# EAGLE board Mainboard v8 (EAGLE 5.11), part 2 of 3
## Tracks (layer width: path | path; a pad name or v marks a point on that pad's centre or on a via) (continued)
M1-B  (via drill 0.3) (continued)
  pour Bottom (no thermals): 101.12,68.42 103.98,68.42 103.98,69.69 106.52,69.69 106.52,65.25 101.12,65.25
  pour Bottom (no thermals): 114.14,78.9 111.92,78.9 110.49,77.47 110.49,65.41 110.33,65.25 109.7,65.25 109.7,77.95 111.6,79.85 114.14,79.85
  pour Top (no thermals): 105.89,69.69 110.49,69.69 110.49,65.25 105.89,65.25
M1-C  (via drill 0.3)
  Top 0.61: v100.17,61.75 100.17,63.34 C6.2 99.86,63.03 IC1.18
  Bottom 0.61: v100.17,61.75 Q5.3
  other vias: 110.02,63.03 110.02,61.75 110.02,60.48 110.02,59.22 110.97,59.22 110.97,60.48 110.97,61.75 110.97,63.03 106.2,63.03 106.2,61.75 106.2,60.48 106.2,59.22
  pour Top (no thermals): 105.89,63.34 111.28,63.34 111.28,58.9 105.89,58.9
  pour Bottom (no thermals): 101.12,62.07 103.98,62.07 103.98,63.34 106.52,63.34 106.52,58.9 101.12,58.9
  pour Bottom (no thermals): 114.14,77 112.24,77 111.76,76.52 111.76,59.69 110.97,58.9 109.7,58.9 109.7,63.03 110.97,64.3 110.97,76.68 112.24,77.95 114.14,77.95
M1-FLT  (via drill 0.3)
  Top 0.254: IC8.13 75.31,39.93 77.63,42.25 77.63,44.61 80.81,47.78 v82.08,47.78 | Q36.3 84.93,62.07 82.23,59.37 | 82.23,59.37 v82.08,59.22 82.23,59.37
  Bottom 0.254: v82.08,47.78 82.08,50.33 83.34,51.59 83.34,56.99 82.08,58.26 v82.08,59.22
M1-H1  (via drill 0.3)
  Top 0.254: IC16.116 73.36,78.09 76.36,75.09 78.9,75.09 | 78.9,75.09 80.49,75.09 83.66,78.27 103.03,78.27 106.2,81.44 113.83,81.44 114.14,81.76 116.36,81.76 116.68,82.08 v116.68,83.34 116.68,82.51 CN1.2 | IC10.13 78.9,73.28 78.9,75.09 | RN2.2 116.68,76.16 v116.68,77 | v116.68,80.17 116.68,79.33 RN1.2
  Bottom 0.254: v116.68,77 v116.68,80.17 v116.68,83.34
M1-H2  (via drill 0.3)
  Top 0.254: IC16.117 73.49,78.59 76.36,75.72 v79.06,75.72 80.17,75.72 83.34,78.9 102.87,78.9 105.89,81.92 113.67,81.92 115.09,83.34 v115.73,83.34 115.73,82.67 CN1.3 | IC10.12 79.53,73.26 79.53,73.98 v79.85,74.3 | RN2.3 115.73,76.32 v115.73,77 | v115.73,80.17 115.73,79.5 RN1.3
  Bottom 0.254: v79.06,75.72 79.85,74.93 v79.85,74.3 | v115.73,77 v115.73,80.17 v115.73,83.34
M1-H3  (via drill 0.3)
  Top 0.254: IC16.118 73.62,79.09 76.36,76.36 v79.85,76.36 83.03,79.53 102.55,79.53 105.41,82.39 113.51,82.39 115.09,83.98 117.32,83.98 117.64,83.66 v117.64,83.34 117.64,82.5 CN1.1 | IC10.9 81.47,74.17 v81.6,74.3 | RN2.1 117.64,76.15 v117.64,77 | v117.64,80.17 117.64,79.33 RN1.1
  Bottom 0.254: v117.64,77 v117.64,80.17 v117.64,83.34 | v79.85,76.36 79.85,76.04 v81.6,74.3
M1-HA  (via drill 0.3)
  Top 0.152: v88.11,81.44 78.58,81.44 78.27,81.76 73.5,81.76 73.17,82.09 IC16.124
  Top 0.406: v90.01,74.45 IC1.2
  Bottom 0.254: v88.11,81.44 88.11,76.36 v90.01,74.45
M1-HB  (via drill 0.3)
  Top 0.152: v86.84,82.71 78.58,82.71 78.27,82.39 74.14,82.39 73.44,83.09 IC16.126
  Top 0.406: v86.52,73.19 IC1.3
  Bottom 0.254: v86.84,82.71 86.84,75.72 86.52,75.41 v86.52,73.19
M1-HC  (via drill 0.3)
  Top 0.152: v85.57,83.98 78.58,83.98 77.63,83.03 74.77,83.03 73.7,84.09 IC16.128
  Top 0.406: v85.25,71.92 IC1.4
  Bottom 0.254: v85.57,83.98 85.57,76.36 85.25,76.04 v85.25,71.92
M1-LA  (via drill 0.3)
  Top 0.152: v87.47,82.08 73.82,82.08 73.3,82.59 IC16.125
  Top 0.406: v90.01,70.64 IC1.5
  Bottom 0.254: v87.47,82.08 87.47,73.19 v90.01,70.64
M1-LB  (via drill 0.3)
  Top 0.152: v86.2,83.34 78.58,83.34 77.95,82.71 74.45,82.71 73.57,83.59 IC16.127
  Top 0.406: v90.01,69.38 IC1.6
  Bottom 0.254: v86.2,83.34 86.2,76.04 85.89,75.72 85.89,72.55 89.06,69.38 v90.01,69.38
M1-LC  (via drill 0.3)
  Top 0.152: v84.93,84.61 78.58,84.61 77.31,83.34 75.09,83.34 73.84,84.59 IC16.129
  Top 0.254: IC1.7 89.06,68.11
  Top 0.406: v90.01,68.11 89.06,68.11 IC1.7
  Bottom 0.254: v84.93,84.61 84.93,76.68 84.61,76.36 84.61,71.6 88.11,68.11 v90.01,68.11
M1-PWR  (via drill 0.3)
  Top 0.406: IC26.5 v100.97,56.99
  Bottom 0.406: v106.52,56.99 105.89,56.99 105.25,56.99 v100.97,56.99
  other vias: 109.7,57.94 109.7,56.99 109.7,56.04
  pour Bottom (no thermals): 109.06,76.04 107.16,76.04 107.16,58.58 106.2,57.63 106.2,56.36 107.16,55.41 110.33,55.41 110.33,58.26 109.06,58.26
  pour Top (no thermals): 106.2,57.63 106.84,58.26 110.33,58.26 110.33,55.41 107.16,55.41 106.2,56.36
M2-A  (via drill 0.3)
  Top 0.61: v19.84,62.71 19.84,61.44 C12.2 20.16,61.75 IC2.26
  Bottom 0.61: v19.84,62.71 17.84,62.71 Q7.1
  other vias: 13.81,63.03 13.81,61.75 13.81,60.48 13.81,59.22 10,63.03 10,59.22 10,60.48 10,61.75 9.37,62.39 9.37,63.66
  pour Bottom (no thermals): 18.89,60.17 16.04,60.17 16.04,58.9 13.5,58.9 13.5,63.34 18.89,63.34
  pour Top (no thermals): 14.13,63.34 14.13,58.9 9.68,58.9 9.68,61.12 9.05,61.75 9.05,64.3 9.68,64.3 10.64,63.34
  pour Bottom (no thermals): 10.32,58.9 9.68,58.9 9.68,61.12 9.05,61.75 9.05,63.66 6.51,66.2 6.51,72.87 7.78,72.87 7.78,66.52 10.32,63.98
M2-A1  (via drill 0.3)
  Top 0.254: v60.48,85.89 62.07,85.89 66,89.82 IC16.10 | v47.15,69.69 37.94,60.48 IC2.2
  Bottom 0.254: v60.48,85.89 50.96,85.89 50.33,86.52 49.05,86.52 48.42,85.89 48.42,70.96 v47.15,69.69
M2-A2  (via drill 0.3)
  Top 0.254: v60.48,87.16 62.07,87.16 65,90.09 IC16.12 | v45.56,69.06 38.26,61.75 IC2.3
  Bottom 0.254: v60.48,87.16 50.96,87.16 50.33,87.79 49.05,87.79 47.15,85.89 47.15,75.72 45.88,74.45 45.88,69.38 v45.56,69.06
M2-A3  (via drill 0.3)
  Top 0.254: v60.48,88.42 62.07,88.42 64,90.36 IC16.14 | v44.61,69.06 38.58,63.03 IC2.4
  Bottom 0.254: v60.48,88.42 50.96,88.42 50.33,89.06 46.2,89.06 44.61,87.47 v44.61,69.06
M2-ADC
  Top 0.254: IC6.2 21.75,56.04 21.43,55.72 21.43,54.45 22.07,53.82 27.47,53.82 35.09,46.2 37.94,46.2 39.3,44.84 RN12.3
M2-AOUT
  Top 0.254: RN12.6 CN7.3 43.1,44.84 43.34,44.61 43.34,43.66 45.24,41.75 45.47,41.53 IC8.26
M2-B  (via drill 0.3)
  Top 0.61: v19.84,67.79 19.84,66.52 C13.2 20.16,66.83 IC2.22
  Bottom 0.61: Q9.2 17.84,67.79 | 17.84,67.79 Q9.3 | 17.84,67.79 v19.84,67.79
  other vias: 13.81,69.38 13.81,68.11 13.81,66.83 13.81,65.56 10,69.38 10,68.11 10,66.83 10,65.56 9.37,66.2 9.37,67.47 9.37,68.74
  pour Bottom (no thermals): 18.89,66.52 16.04,66.52 16.04,65.25 13.5,65.25 13.5,69.69 18.89,69.69
  pour Top (no thermals): 14.13,69.69 14.13,65.25 10,65.25 8.73,66.52 8.73,68.42 10,69.69
  pour Bottom (no thermals): 5.88,73.82 7.94,73.82 8.26,73.5 8.26,66.99 10,65.25 10.32,65.25 10.32,69.69 10,70.01 9.68,70.01 9.05,70.64 9.05,74.14 8.1,75.09 5.88,75.09
M2-B1  (via drill 0.3)
  Top 0.254: v61.12,86.52 62.07,86.52 65.5,89.95 IC16.11 | v47.15,70.64 45.24,70.64 38.74,64.14 32.55,64.14 32.39,64.3 IC2.5
  Bottom 0.254: v61.12,86.52 50.96,86.52 50.33,87.16 49.05,87.16 47.78,85.89 47.78,71.28 v47.15,70.64
M2-B2  (via drill 0.3)
  Top 0.254: v61.12,87.79 62.07,87.79 64.5,90.22 IC16.13 | v45.24,71.92 45.24,71.6 38.26,64.61 33.5,64.61 32.55,65.56 IC2.6
  Bottom 0.254: v61.12,87.79 50.96,87.79 50.33,88.42 46.2,88.42 45.24,87.47 v45.24,71.92
M2-B3  (via drill 0.3)
  Top 0.254: v61.12,89.06 62.07,89.06 63.5,90.49 IC16.15 | IC2.7 32.7,66.83 33.5,66.04 34.13,65.41 34.45,65.09 37.78,65.09 v43.98,71.28
  Bottom 0.254: v61.12,89.06 50.96,89.06 50.33,89.69 46.2,89.69 43.98,87.47 v43.98,71.28
M2-C  (via drill 0.3)
  Top 0.61: IC2.18 20.16,71.92 C14.2 19.84,71.59 v19.84,73.19
  Bottom 0.254: M2.6 7.78,77
  Bottom 0.61: M2.7 M2.6 | Q11.2 Q11.3 v19.84,73.19
  other vias: 13.81,75.72 13.81,74.45 13.81,73.19 13.81,71.92 10,75.72 10,74.45 10,73.19 9.37,75.09 10,71.92
  pour Bottom (no thermals): 18.89,72.87 16.04,72.87 16.04,71.6 13.5,71.6 13.5,76.04 18.89,76.04
  pour Top (no thermals): 14.13,71.6 14.13,76.04 10,76.04 10,73.5 9.37,72.87 9.37,71.6
  pour Bottom (no thermals): 5.88,76.04 7.78,76.04 9.53,74.3 9.53,71.76 9.68,71.6 10.16,71.6 10.32,71.76 10.32,75.72 9.05,77 5.88,77
M2-FLT  (via drill 0.3)
  Top 0.254: v38.26,42.7 38.26,42.07 40.96,39.37 51.59,39.37 55.09,35.88 59.69,35.88 61.34,37.53 IC8.31 | v38.26,67.95 37.31,66.98 Q37.3
  Bottom 0.254: v38.26,42.7 v38.26,67.95
M2-H1  (via drill 0.3)
  Top 0.254: v62.39,90.33 62.39,92.23 62,92.62 IC16.18 | IC11.12 39.52,87.81 v39.53,87.79 | RN4.2 4.29,79.73 v4.29,78.9 | v4.29,75.72 4.29,76.56 RN3.2 | CN2.2 4.29,73.38 v4.29,72.55 4.92,71.92 6.35,71.92 6.99,72.55 6.99,74.61 10,77.63 v27.78,77.63
  Bottom 0.254: v62.39,90.33 50.96,90.33 49.69,91.6 43.34,91.6 v39.53,87.79 29.37,77.63 v27.78,77.63 | v4.29,78.9 v4.29,75.72 v4.29,72.55
M2-H2  (via drill 0.3)
  Top 0.254: v61.75,89.69 61.75,92.23 61.5,92.48 IC16.19 | IC11.9 41.47,88.77 v41.44,88.74 | v3.34,75.72 3.34,76.36 | 3.34,76.36 3.34,76.4 | RN4.1 3.34,79.74 v3.34,78.9 | RN3.1 3.4,76.43 3.34,76.36 | CN2.1 3.34,73.39 v3.34,72.55 4.61,71.28 6.51,71.28 7.46,72.23 7.46,74.3 10.16,77 v28.42,77
  Bottom 0.254: v61.75,89.69 50.96,89.69 50.33,90.33 43.02,90.33 v41.44,88.74 29.69,77 v28.42,77 | v3.34,78.9 v3.34,75.72 v3.34,72.55
M2-H3  (via drill 0.3)
  Top 0.254: v61.12,90.97 61.12,92.23 61,92.35 IC16.20 | IC11.13 38.87,88.08 v38.58,87.79 | RN4.3 5.24,79.58 v5.24,78.9 | v5.24,75.72 5.24,76.4 RN3.3 | CN2.3 5.24,73.23 v5.24,72.55 6.19,72.55 6.51,72.87 6.51,74.93 9.84,78.27 v27.15,78.27
  Bottom 0.254: v61.12,90.97 50.96,90.97 49.69,92.23 43.02,92.23 v38.58,87.79 29.05,78.27 v27.15,78.27 | v5.24,78.9 v5.24,75.72 v5.24,72.55
M2-PWR  (via drill 0.3)
  Top 0.406: v19.21,55.72 19.84,55.09 IC6.5
  Bottom 0.406: v13.5,56.99 14.77,55.72 v19.21,55.72
  other vias: 10.32,55.72 10.32,56.67 10.32,57.63
  pour Bottom (no thermals): 10.95,76.04 12.86,76.04 12.86,58.58 13.81,57.63 13.81,56.36 12.86,55.41 9.68,55.41 9.68,58.26 10.95,58.26
  pour Top (no thermals): 13.81,57.63 13.18,58.26 9.68,58.26 9.68,55.41 12.86,55.41 13.81,56.36
M3-A  (via drill 0.3)
  Top 0.61: v19.84,31.59 19.84,30.32 C20.2 20.16,30.64 IC3.26
  Bottom 0.61: v19.84,31.59 17.84,31.59 Q13.1
  other vias: 13.81,31.91 13.81,30.64 13.81,29.37 13.81,28.1 13.81,26.83 12.86,26.83 14.77,26.83 13.81,25.88 14.77,25.88
  pour Bottom (no thermals): 15.72,22.38 14.13,22.38 14.13,24.92 11.91,27.15 13.5,27.15 13.5,27.78 16.04,27.78 16.04,26.83 15.72,26.51
  pour Bottom (no thermals): 18.89,29.05 16.04,29.05 16.04,27.78 13.5,27.78 13.5,32.23 18.89,32.23
  pour Top (no thermals): 10.64,32.23 14.13,32.23 14.13,27.78 15.72,26.2 15.72,25.56 13.5,25.56 10.64,28.42
M3-A1  (via drill 0.3)
  Top 0.254: v59.22,84.61 59.85,85.25 59.85,91.6 60.5,92.25 IC16.21
  Top 0.406: IC3.2 34.13,29.37 v35.4,30.64
  Bottom 0.254: v59.22,84.61 52.55,84.61 50.33,82.39 50.33,70.01 44.61,64.3 44.61,38.58 36.67,30.64 v35.4,30.64
M3-A2  (via drill 0.3)
  Top 0.254: v49.37,85.89 49.58,86.09 IC16.49
  Top 0.406: IC3.3 34.13,30.64 v34.77,31.27
  Bottom 0.254: v49.37,85.89 49.05,85.57 49.05,70.64 43.34,64.93 43.34,39.21 36.67,32.55 34.77,32.55 v34.77,31.27
M3-A3  (via drill 0.3)
  Top 0.254: v43.34,83.03 43.98,83.66 48.74,83.66 49.17,84.09 IC16.53
  Top 0.406: IC3.4 v33.5,31.91
  Bottom 0.254: v43.34,83.03 42.07,81.76 42.07,41.75 33.5,33.18 v33.5,31.91
M3-ADC
  Top 0.254: IC7.2 21.75,47.78 21.43,48.1 21.43,49.37 22.07,50.01 30.32,50.01 34.77,45.56 37.62,45.56 39.14,44.05 RN12.4
M3-AOUT
  Top 0.254: IC8.27 45.95,40.73 45.31,40.73 42.66,43.38 CN7.4 RN12.5
M3-B  (via drill 0.3)
  Top 0.61: v19.84,36.67 19.84,35.4 C21.2 20.16,35.72 IC3.22
  Bottom 0.61: 17.84,36.67 Q15.2 | 17.84,36.67 Q15.3 | v19.84,36.67 17.84,36.67
  other vias: 13.81,38.26 13.81,36.99 13.81,35.72 13.81,34.45 9.68,38.26 9.05,37.62 9.68,36.99 9.05,36.35 9.68,35.72 9.05,35.09 9.68,34.45 12.23,24.92 13.18,24.92 11.91,25.88
  pour Bottom (no thermals): 13.5,22.38 12.23,22.38 12.23,24.92 8.1,29.05 8.1,38.58 10,38.58 10,28.1 13.5,24.61
  pour Bottom (no thermals): 18.89,35.4 16.04,35.4 16.04,34.13 13.5,34.13 13.5,38.58 18.89,38.58
  pour Top (no thermals): 14.13,38.58 8.1,38.58 8.1,35.72 9.68,34.13 14.13,34.13
  pour Top (no thermals): 13.5,24.29 12.23,24.29 12.23,24.92 8.1,29.05 8.1,35.72 10,35.72 10,28.1 13.5,24.61
M3-B1  (via drill 0.3)
  Top 0.254: v58.58,85.25 59.22,85.89 59.22,91.6 60,92.39 IC16.22
  Top 0.406: IC3.5 34.13,33.18 v35.4,31.91
  Bottom 0.254: v58.58,85.25 52.23,85.25 49.69,82.71 49.69,70.33 43.98,64.61 43.98,38.9 36.99,31.91 v35.4,31.91
M3-B2  (via drill 0.3)
  Top 0.254: v43.34,83.98 43.5,84.14 45.09,84.14 46.52,85.57 48.74,85.57 49.05,85.25 49.69,85.25 50.03,85.59 IC16.50
  Top 0.406: IC3.6 33.18,34.45 v33.5,34.13
  Bottom 0.254: v43.34,83.98 41.44,82.08 41.44,42.07 v33.5,34.13
M3-B3  (via drill 0.3)
  Top 0.254: v43.34,82.08 44.45,83.19 48.9,83.19 49.3,83.59 IC16.54
  Top 0.406: IC3.7 33.18,35.72 35.09,33.81 v35.4,33.81
  Bottom 0.254: v35.4,33.81 36.99,33.81 42.7,39.53 42.7,81.44 v43.34,82.08
M3-C  (via drill 0.3)
  Top 0.61: v19.84,42.07 19.84,40.48 C22.2 20.16,40.8 IC3.18
  Bottom 0.254: M3.6 10.32,24.29
  Bottom 0.61: Q17.2 Q17.3 v19.84,42.07
  other vias: 13.81,44.61 13.81,43.34 13.81,42.07 13.81,40.8 9.68,44.61 9.68,43.34 9.68,42.07 9.68,40.8 9.05,41.44 9.05,42.7 9.05,43.98
  pour Bottom (no thermals): 11.59,22.38 10.32,22.38 10.32,24.29 5.24,29.37 5.24,43.66 6.51,44.93 10.32,44.93 10.32,40.48 7.14,40.48 7.14,29.05 11.59,24.61
  pour Bottom (no thermals): 18.89,41.75 16.04,41.75 16.04,40.48 13.5,40.48 13.5,44.93 18.89,44.93
  pour Top (no thermals): 14.13,40.48 14.13,44.93 8.73,44.93 8.73,40.48
M3-FLT
  Top 0.254: IC8.32 61.65,36.73 60.17,35.24 54.77,35.24 51.28,38.74 45.4,38.74 40.16,38.74 38.9,37.47 38.57,37.47 Q38.3
M3-H1  (via drill 0.3)
  Top 0.254: v40.8,77.31 48.74,77.31 49.02,77.59 IC16.66 | RN6.2 9.49,19.53 v10.32,19.53 | v13.5,19.53 12.66,19.53 RN5.2 | CN3.2 15.84,19.53 v16.67,19.53 17.46,19.53 21.27,23.34 v28.1,23.34 | v40.16,82.71 IC11.4
  Bottom 0.254: v28.1,23.34 32.86,28.1 32.86,34.45 40.8,42.39 40.8,50.96 v40.8,77.31 40.8,82.08 v40.16,82.71 | v10.32,19.53 v13.5,19.53 v16.67,19.53
M3-H2  (via drill 0.3)
  Top 0.254: v40.16,76.68 49.05,76.68 49.47,77.09 IC16.67 | RN6.3 9.64,20.48 v10.32,20.48 | v13.5,20.48 12.82,20.48 RN5.3 | CN3.3 15.99,20.48 v16.67,20.48 17.62,20.48 21.11,23.97 v27.47,23.97 | v39.21,82.71 38.87,83.06 IC11.2
  Bottom 0.254: v10.32,20.48 v13.5,20.48 v16.67,20.48 | v39.21,82.71 39.21,82.39 40.16,81.44 v40.16,76.68 40.16,51.28 40.16,42.7 32.07,34.61 32.07,28.1 27.94,23.97 v27.47,23.97
M3-H3  (via drill 0.3)
  Top 0.254: v39.53,76.04 49.37,76.04 49.92,76.59 IC16.68 | RN6.1 9.48,18.57 v10.32,18.57 | v13.5,18.57 12.65,18.57 RN5.1 | CN3.1 15.83,18.57 v16.67,18.57 17.3,18.57 21.43,22.7 v26.83,22.7 | v38.26,82.71 38.22,82.75 IC11.1
  Bottom 0.254: v10.32,18.57 v13.5,18.57 v16.67,18.57 | v38.26,82.71 38.26,82.39 39.53,81.12 v39.53,76.04 39.53,51.59 39.53,43.02 31.27,34.77 31.27,28.1 27.78,24.61 27.15,24.61 26.83,24.29 v26.83,22.7
M4-A  (via drill 0.3)
  Top 0.61: v100.17,42.07 100.17,43.66 C28.2 99.86,43.34 IC4.26
  Bottom 0.61: M4.11 M4.10 | v100.17,42.07 Q19.1
  other vias: 106.2,45.88 106.2,44.61 106.2,43.34 106.2,42.07 110.33,45.88 111.28,45.88 110.33,44.61 111.28,44.61 110.33,43.34 111.28,43.34 110.33,42.07 111.28,42.07
  pour Bottom (no thermals): 114.78,22.38 113.19,22.38 113.19,28.73 112.24,29.69 112.24,41.75 110.02,41.75 110.02,46.2 114.46,46.2 114.46,29.05 114.78,28.73
  pour Top (no thermals): 105.89,46.2 105.89,41.75 114.46,41.75 114.46,46.2
  pour Bottom (no thermals): 101.12,44.93 103.98,44.93 103.98,46.2 106.52,46.2 106.52,41.75 101.12,41.75
M4-A1  (via drill 0.3)
  Top 0.254: v81.44,47.15 83.98,44.61 IC4.2 | v53.82,80.49 53.82,81.76 52.98,82.59 IC16.56 | v77,64.93 76.04,65.88 71.28,65.88 70.64,66.52 v70.49,66.52
  Bottom 0.254: v53.82,80.49 53.82,80.17 57.31,76.68 61.12,76.68 63.03,74.77 63.03,73.5 67.47,69.06 67.47,67.63 68.58,66.52 v70.49,66.52 | v77,64.93 81.44,60.48 81.44,58.1 82.87,56.67 82.87,51.91 81.44,50.48 v81.44,47.15
M4-A2  (via drill 0.3)
  Top 0.254: v77,63.03 76.68,62.71 70.17,62.71 67.15,65.72 62.55,65.72 60.8,67.47 60.8,70.64 60,71.44 IC16.87 | IC4.3 85.41,43.34 84.61,44.13 83.19,44.13 v80.81,46.52
  Bottom 0.254: v77,63.03 80.81,59.22 80.81,57.94 82.39,56.36 82.39,52.23 80.81,50.64 v80.81,46.52
M4-A3  (via drill 0.3)
  Top 0.254: v76.36,63.98 70.17,63.98 67.47,66.68 62.87,66.68 61.75,67.79 61.75,70.96 61,71.71 IC16.89 | IC4.4 85.89,42.07 84.3,43.66 82.39,43.66 v80.17,45.88
  Bottom 0.254: v76.36,63.98 76.36,62.39 80.17,58.58 80.17,57.79 81.92,56.04 81.92,52.55 80.17,50.8 v80.17,45.88
M4-ADC
  Top 0.254: IC27.2 98.27,49.05 98.58,49.37 98.58,50.33 97.63,51.28 96.16,51.28 RN13.1
M4-AOUT  (via drill 0.3)
  Top 0.254: IC8.23 64.83,43.12 v65.56,42.39 | v71.28,43.66 75.72,43.66 80.49,48.42 83.98,48.42 90.65,48.42 92.55,50.33 93.55,51.32 CN8.1 RN13.8
  Bottom 0.254: v65.56,42.39 70.01,42.39 v71.28,43.66
M4-B  (via drill 0.3)
  Top 0.61: v100.17,36.99 100.17,38.58 C29.2 99.86,38.26 IC4.22
  Bottom 0.61: M4.8 M4.9 | Q21.3 Q21.2 v100.17,36.99
  other vias: 106.2,39.53 106.2,38.26 106.2,36.99 106.2,35.72 110.33,39.53 110.97,38.9 110.97,37.62 110.33,38.26 110.33,36.99 110.33,35.72 110.97,36.35
  pour Bottom (no thermals): 111.28,22.38 111.28,27.15 110.02,28.42 110.02,39.85 111.28,39.85 111.28,29.37 112.56,28.1 112.56,22.38
  pour Top (no thermals): 105.89,39.85 105.89,35.4 111.28,35.4 111.28,39.85
  pour Bottom (no thermals): 101.12,38.58 103.98,38.58 103.98,39.85 106.52,39.85 106.52,35.4 101.12,35.4
M4-B1  (via drill 0.3)
  Top 0.254: v53.18,81.12 52.21,82.09 IC16.57 | v75.72,64.61 75.09,65.25 70.96,65.25 70.33,65.88 v69.85,65.88 | IC4.5 86.36,40.8 83.98,43.18 81.6,43.18 v79.53,45.24
  Bottom 0.254: v75.72,64.61 75.72,62.39 78.11,60.01 78.11,47.94 79.53,46.52 v79.53,45.24 | v69.85,65.88 68.42,65.88 66.83,67.47 66.83,68.74 62.39,73.19 62.39,74.45 60.8,76.04 56.99,76.04 53.18,79.85 v53.18,81.12
M4-B2  (via drill 0.3)
  Top 0.254: v75.09,63.34 70.17,63.34 67.31,66.2 62.71,66.2 61.28,67.63 61.28,70.8 60.5,71.58 IC16.88 | IC4.6 86.84,39.53 83.66,42.7 80.81,42.7 v78.9,44.61
  Bottom 0.254: v75.09,63.34 75.09,62.39 77.63,59.85 77.63,47.63 78.9,46.36 v78.9,44.61
M4-B3  (via drill 0.3)
  Top 0.254: v74.45,64.61 70.17,64.61 67.63,67.15 63.03,67.15 62.23,67.95 62.23,71.12 61.5,71.85 IC16.90 | IC4.7 87.31,38.26 83.34,42.23 80.01,42.23 v78.27,43.98
  Bottom 0.254: v74.45,64.61 74.45,62.39 77.15,59.69 77.15,47.31 78.27,46.2 v78.27,43.98
M4-C  (via drill 0.3)
  Top 0.61: v100.17,31.91 100.17,33.5 C30.2 99.86,33.18 IC4.18
  Bottom 0.61: M4.7 M4.6 | Q23.2 Q23.3 v100.17,31.91
  other vias: 106.2,33.18 106.2,31.91 106.2,30.64 106.2,29.37 109.06,27.78 109.7,27.15 110.33,26.51 109.06,26.51 108.43,27.15 107.79,27.78
  pour Bottom (no thermals): 109.38,22.38 109.06,22.7 109.06,25.88 106.84,28.1 101.76,28.1 101.12,28.73 101.12,29.05 106.52,29.05 107.16,28.42 109.06,28.42 110.65,26.83 110.65,22.7 110.33,22.38
  pour Top (no thermals): 105.89,33.5 105.89,29.05 106.84,28.1 107.47,28.1 108.43,27.15 109.38,26.2 110.65,26.2 110.65,26.83 109.38,28.1 109.38,33.5
  pour Bottom (no thermals): 101.12,32.23 103.98,32.23 103.98,33.5 106.52,33.5 106.52,29.05 101.12,29.05
M4-FLT
  Top 0.254: Q39.3 78.9,37.94 78.27,38.58 77.71,39.13 IC8.12
M4-H1  (via drill 0.3)
  Top 0.254: v81.44,33.18 82.08,32.55 86.2,28.42 87.47,27.15 92.55,27.15 93.19,27.78 106.04,27.78 110.17,23.66 112.87,23.66 115.09,21.43 115.09,20.8 v114.14,19.84 113.31,19.84 CN4.2 | IC16.82 57.5,74.97 v57.94,75.41 | v69.38,61.44 v73.19,61.44 77.63,61.44 78.87,62.68 IC10.2 | RN8.2 106.96,19.84 v107.79,19.84 | v110.97,19.84 110.14,19.84 RN7.2
  Bottom 0.254: v73.19,61.44 73.19,61.12 75.72,58.58 75.72,46.36 76.36,45.72 76.36,38.26 v81.44,33.18 | v57.94,75.41 58.58,75.41 59.22,74.77 60.17,74.77 61.12,73.82 61.12,72.55 64.61,69.06 64.61,66.83 69.38,62.07 v69.38,61.44 | v107.79,19.84 v110.97,19.84 v114.14,19.84
M4-H2  (via drill 0.3)
  Top 0.254: v81.44,34.13 82.71,32.86 87.95,27.62 88.27,27.62 92.39,27.62 93.19,28.42 106.2,28.42 110.33,24.29 113.19,24.29 115.73,21.75 115.73,19.84 114.78,18.89 v114.14,18.89 113.3,18.89 CN4.1 | IC16.85 59,74.88 v59.53,75.41 | v70.01,62.07 v73.82,62.07 77.63,62.07 78.22,62.66 IC10.1 | RN8.1 106.95,18.89 v107.79,18.89 | v110.97,18.89 110.12,18.89 RN7.1
  Bottom 0.254: v81.44,34.13 77,38.58 77,45.88 76.2,46.67 76.2,59.06 73.82,61.44 v73.82,62.07 | v59.53,75.41 60.48,75.41 61.75,74.14 61.75,72.87 66.2,68.42 66.2,66.2 70.01,62.39 v70.01,62.07 | v107.79,18.89 v110.97,18.89 v114.14,18.89
M4-H3  (via drill 0.3)
  Top 0.254: v81.44,32.23 85.57,28.1 87,26.67 92.71,26.67 93.19,27.15 105.89,27.15 110.02,23.02 112.71,23.02 114.14,21.59 v114.14,20.8 113.47,20.8 CN4.3 | IC16.86 59.5,73.79 v59.85,74.14 | v68.74,60.8 v72.55,60.8 77.63,60.8 80.17,63.34 IC10.4 | RN8.3 107.11,20.8 v107.79,20.8 | v110.97,20.8 110.29,20.8 RN7.3
  Bottom 0.254: v81.44,32.23 75.72,37.94 75.72,45.56 75.25,46.04 75.25,58.1 v72.55,60.8 | v59.85,74.14 60.48,73.5 60.48,72.23 63.98,68.74 63.98,66.52 68.74,61.75 v68.74,60.8 | v107.79,20.8 v110.97,20.8 v114.14,20.8
M4-PWR  (via drill 0.3)
  Top 0.406: v100.81,49.37 100.17,50.01 IC27.5
  Bottom 0.406: v106.52,48.1 105.25,49.37 v100.81,49.37
  other vias: 109.7,49.37 109.7,48.42 109.7,47.47
  pour Bottom (no thermals): 109.06,29.05 107.16,29.05 107.16,46.52 106.2,47.47 106.2,48.74 107.16,49.69 110.33,49.69 110.33,46.83 109.06,46.83
  pour Top (no thermals): 106.2,47.47 106.84,46.83 110.33,46.83 110.33,49.69 107.16,49.69 106.2,48.74
M5-A  (via drill 0.3)
  Top 0.61: IC5.26 20.16,90.97 C36.2 19.84,90.64 v19.84,91.92
  Bottom 0.61: M5.8 8.1,88.11 8.41,88.42 | v19.84,91.92 17.84,91.92 Q25.1
  other vias: 13.81,92.23 13.81,90.97 13.81,89.69 13.81,88.42 9.68,90.97 9.05,90.33 9.68,89.69 9.68,88.42 9.05,89.06 9.05,87.79
  pour Bottom (no thermals): 2.06,88.74 6.83,88.74 10.32,92.23 10.32,88.42 8.73,86.84 7.78,86.84 7.14,87.47 2.06,87.47 1.75,87.79 1.75,88.42
  pour Bottom (no thermals): 18.89,89.38 16.04,89.38 16.04,88.11 13.5,88.11 13.5,92.55 18.89,92.55
  pour Top (no thermals): 14.13,92.55 10.64,92.55 8.41,90.33 8.41,87.79 9.05,87.16 10,88.11 14.13,88.11
M5-A1  (via drill 0.3)
  Top 0.254: v71.92,97.95 71.92,93.82 70.33,92.23 70.33,91.6 71.33,90.59 IC16.141
  Top 0.406: IC5.2 v34.13,89.69
  Bottom 0.254: v71.92,97.95 71.92,101.12 68.74,104.3 36.67,104.3 34.13,101.76 v34.13,89.69
M5-A2  (via drill 0.3)
  Top 0.254: v71.28,98.58 71.28,95.73 70.5,94.95 IC16.1
  Top 0.406: IC5.3 v34.77,90.97
  Bottom 0.254: v71.28,98.58 71.28,100.81 68.42,103.67 36.99,103.67 34.77,101.44 v34.77,90.97
M5-A3  (via drill 0.3)
  Top 0.254: v70.01,98.58 70.01,95.73 69.5,95.22 IC16.3
  Top 0.406: IC5.4 v36.04,92.23
  Bottom 0.254: v70.01,98.58 70.01,100.17 67.79,102.39 37.62,102.39 36.04,100.81 v36.04,92.23
M5-ADC  (via drill 0.3)
  Top 0.254: IC28.2 21.75,85.25 21.43,84.93 21.43,83.66 22.7,82.39 33.81,82.39 v35.72,80.49 | v37.62,47.47 38.58,46.52 40.05,46.52 RN12.1
  Bottom 0.254: v35.72,80.49 37.62,78.58 v37.62,47.47
M5-AOUT
  Top 0.254: RN12.8 CN7.1 42.79,46.45 43.34,46.99 44.61,46.99 45.88,45.72 45.88,43.34 46.83,42.39 62.48,42.39 IC8.25
M5-B  (via drill 0.3)
  Top 0.61: v19.84,97 19.84,95.72 C37.2 20.16,96.05 IC5.22
  Bottom 0.61: M5.7 4.61,90.65 9.68,95.73 | v19.84,97 17.84,97 Q27.2
  other vias: 13.81,98.58 13.81,97.31 13.81,96.05 13.81,94.78 9.68,97.95 9.05,97.31 9.68,96.68 9.05,96.05 9.68,95.41 9.05,94.78 9.68,94.14
  pour Bottom (no thermals): 2.06,91.28 4.61,91.28 8.41,95.09 8.41,97.31 10,98.9 10.32,98.9 10.32,94.46 5.88,90.01 2.06,90.01 1.75,90.33 1.75,90.97
  pour Bottom (no thermals): 18.89,95.73 16.04,95.73 16.04,94.46 13.5,94.46 13.5,98.9 18.89,98.9
  pour Top (no thermals): 14.13,94.46 13.5,93.82 9.05,93.82 8.41,94.46 8.41,97.31 10,98.9 14.13,98.9
M5-B1  (via drill 0.3)
  Top 0.254: v72.55,98.58 72.55,93.82 70.96,92.23 70.96,91.6 71.47,91.09 IC16.142
  Top 0.406: IC5.5 v33.5,93.5
  Bottom 0.254: v72.55,98.58 72.55,101.44 69.06,104.94 36.35,104.94 33.5,102.08 v33.5,93.5
M5-B2  (via drill 0.3)
  Top 0.254: v70.64,97.95 70.64,95.73 70,95.09 IC16.2
  Top 0.406: IC5.6 v35.4,94.78
  Bottom 0.254: v70.64,97.95 70.64,100.49 68.11,103.03 37.31,103.03 35.4,101.12 v35.4,94.78
M5-B3  (via drill 0.3)
  Top 0.254: v69.38,99.22 69.38,95.73 69,95.36 IC16.4
  Top 0.406: IC5.7 v36.67,96.05
  Bottom 0.254: v69.38,99.22 69.38,99.86 67.47,101.76 37.94,101.76 36.67,100.49 v36.67,96.05
M5-C  (via drill 0.3)
  Top 0.61: v19.84,102.39 19.84,101.12 C38.2 20.16,101.12 IC5.18
  Bottom 0.61: M5.6 3.97,93.19 | v19.84,102.39 Q29.3
  other vias: 13.81,104.94 13.81,103.67 13.81,102.39 13.81,101.12 9.68,101.76 9.05,102.39 9.68,103.03 9.05,103.67 9.68,104.3 9.05,101.12 9.68,100.49
  pour Bottom (no thermals): 2.06,93.82 3.97,93.82 5.24,95.09 5.24,100.49 10,105.25 10.32,105.25 10.32,100.49 7.78,97.95 7.78,95.73 4.61,92.55 2.06,92.55 1.75,92.87 1.75,93.5
  pour Bottom (no thermals): 18.89,102.08 16.04,102.08 16.04,100.81 13.5,100.81 13.5,105.25 18.89,105.25
  pour Top (no thermals): 14.13,100.81 13.5,100.17 9.05,100.17 8.41,100.81 8.41,103.67 10,105.25 14.13,105.25
M5-FLT  (via drill 0.3)
  Top 0.254: IC8.30 61.19,38.33 59.37,36.51 55.41,36.51 51.91,40.01 41.28,40.01 38.9,42.39 v38.9,43.34 | Q40.3 33.01,84.78 v36.67,81.12
  Bottom 0.254: v38.9,43.34 38.9,78.9 v36.67,81.12
M5-H1  (via drill 0.3)
  Top 0.254: v66.83,91.28 68.5,92.95 IC16.5 | v43.02,98.74 43.05,98.77 IC12.9 43.05,102.05 41.59,103.51 35.72,103.51 33.5,105.73 30.32,105.73 29.69,106.36 22.54,106.36 21.43,107.47 v19.53,107.47 18.7,107.47 CN5.2 | RN10.2 12.35,107.47 v13.18,107.47 | v16.35,107.47 15.52,107.47 RN9.2
  Bottom 0.254: v66.83,91.28 67.47,91.92 67.47,96.36 65.88,97.95 43.82,97.95 v43.02,98.74 | v13.18,107.47 v16.35,107.47 v19.53,107.47
M5-H2  (via drill 0.3)
  Top 0.254: v29.37,105.73 21.59,105.73 21.11,106.2 20.8,106.52 v19.53,106.52 18.68,106.52 CN5.1 | IC16.58 49.85,81.59 48.74,82.71 44.93,82.71 44.29,82.08 43.66,81.44 38.26,81.44 35.09,84.61 v35.09,88.74 35.09,89.06 38.26,92.23 41.44,92.23 42.4,93.2 IC12.5 | RN10.1 12.34,106.52 v13.18,106.52 | v16.35,106.52 15.51,106.52 RN9.1
  Bottom 0.254: v29.37,105.73 29.53,105.73 31.27,103.98 31.27,90.97 33.5,88.74 v35.09,88.74 | v13.18,106.52 v16.35,106.52 v19.53,106.52
M5-H3  (via drill 0.3)
  Top 0.254: IC16.59 49.72,81.09 48.58,82.23 45.09,82.23 43.82,80.96 37.94,80.96 35.4,83.5 34.45,84.46 v34.45,88.11 34.45,89.06 38.26,92.87 41.28,92.87 41.75,93.35 IC12.4 | RN10.3 12.5,108.43 v13.18,108.43 | v16.35,108.43 15.68,108.43 RN9.3 | CN5.3 18.85,108.43 v19.53,108.43
  Bottom 0.254: v13.18,108.43 v16.35,108.43 v19.53,108.43 21.75,108.43 22.38,107.79 23.18,107 27.15,107 30.64,103.51 30.64,90.97 33.5,88.11 v34.45,88.11
M5-PWR  (via drill 0.3)
  Top 0.406: v19.21,84.93 19.84,84.3 IC28.5
  Bottom 0.406: v13.5,86.2 14.77,84.93 v19.21,84.93
  other vias: 10.32,84.93 10.32,85.89 10.32,86.84
  pour Bottom (no thermals): 10.95,105.25 12.86,105.25 12.86,87.79 13.81,86.84 13.81,85.57 12.86,84.61 9.68,84.61 9.68,86.84 10.32,87.47 10.95,87.47
  pour Top (no thermals): 13.81,86.84 13.18,87.47 10.32,87.47 9.68,86.84 9.68,84.61 12.86,84.61 13.81,85.57
M-AREF
  Top 0.254: C46.1 | C46.1 67.23,45.8 IC8.20 | D21.1 62.7,46.51 64.93,48.74 C45.+ 66.52,48.74 66.52,48.26 | C46.1 66.52,46.51 66.52,48.26 | 66.52,48.26 66.68,48.1 R46.1
M-AVCC
  Top 0.254: R46.2 70.32,48.11 | IC8.18 68.83,45.66 C44.1 69.06,46.04 69.53,46.52 69.53,47.63 R46.2 | L1.2 70.01,49.86 R46.2
M-CS  (via drill 0.3)
  Top 0.254: v50.64,68.42 50.64,71.92 53.18,74.45 53.18,75.09 52.18,76.09 IC16.69 | IC8.14 71.2,40.8 v73.19,40.8
  Bottom 0.254: v50.64,68.42 50.64,60.17 51.59,59.22 53.5,59.22 57.31,55.41 64.61,55.41 73.19,46.83 v73.19,40.8
M-LED1  (via drill 0.3)
  Top 0.254: IC8.9 69.75,36.73 v69.69,36.67 | R44.1 v62.23,31.91
  Bottom 0.254: v69.69,36.67 66.2,36.67 62.23,32.7 v62.23,31.91
M-LED2  (via drill 0.3)
  Top 0.254: IC8.10 69.79,37.53 v69.69,37.62 | R45.1 v62.23,33.81
  Bottom 0.254: v69.69,37.62 66.04,37.62 v62.23,33.81
M-RST  (via drill 0.3)
  Top 0.254: v49.37,67.79 49.37,71.28 52.55,74.45 52.55,75.09 52.04,75.59 IC16.70 | IC8.29 60.57,39.13 v60.48,39.21 58.58,39.21 | R43.1 58.58,39.21 | 58.58,39.21 C42.1
  Bottom 0.254: v49.37,67.79 49.37,59.53 50.96,57.94 52.87,57.94 57.63,53.18 57.63,43.98 60.48,41.12 v60.48,39.21
M-XTAL
  Top 0.254: 71.36,29.47 QG1.3 71.91,30.65 68.83,33.72 IC8.7
MAIN-RX  (via drill 0.3)
  Top 0.254: IC16.122 69.4,81.09 68.74,81.76 v68.74,89.06
  Bottom 0.254: v68.74,89.06 68.74,90.65 74.45,96.36 74.45,102.39 70.01,106.84 69.06,107.79 68.74,108.11 65.56,108.11 63.66,110.02 EXT.5
MAIN-TX  (via drill 0.3)
  Top 0.254: IC16.119 69.95,79.59 68.11,81.44 v68.11,88.42
  Bottom 0.254: v68.11,88.42 68.11,90.97 73.82,96.68 73.82,102.08 68.42,107.47 62.87,107.47 61.12,109.22 EXT.3
N$1  (via drill 0.3)
  Top 0.406: v19.05,46.83 IC7.5
  Bottom 0.406: v13.5,46.83 v19.05,46.83
  other vias: 10.32,45.88 10.32,46.83 10.32,47.78
  pour Bottom (no thermals): 10.95,27.78 12.86,27.78 12.86,45.24 13.81,46.2 13.81,47.47 12.86,48.42 9.68,48.42 9.68,45.56 10.95,45.56
  pour Top (no thermals): 13.81,46.2 13.18,45.56 9.68,45.56 9.68,48.42 12.86,48.42 13.81,47.47
N$2  (via drill 0.3)
  Top 0.61: v95.73,74.45 IC1.27
  Bottom 0.61: Q1.4 99.54,75.72 98.27,74.45 v95.73,74.45
N$4  (via drill 0.3)
  Top 0.61: IC1.16 96.05,60.48 94.78,61.75 94.78,70.96 v95.73,71.92 | v101.44,70.64 101.44,71.92 Q2.4
  Bottom 0.61: v95.73,71.92 97,70.64 v101.44,70.64
N$5  (via drill 0.3)
  Top 0.61: v95.73,69.38 IC1.23
  Bottom 0.61: v95.73,69.38 Q3.4
N$6
  Top 0.406: IC18.2 21.11,10 C83.1
N$7
  Top 0.254: Q35.B R87.2 R83.2
N$8  (via drill 0.3)
  Top 0.254: v117.48,73.82 117.48,74.64 RN2.8
  Bottom 0.254: v117.48,73.82 116.52,72.71 114.94,72.71 114.65,73 M1.2
N$9  (via drill 0.3)
  Top 0.254: v116.52,73.82 116.52,74.49 RN2.7
  Bottom 0.254: v116.52,73.82 115.89,73.19 115.25,73.19 114.44,74 M1.3
N$10  (via drill 0.3)
  Top 0.254: v115.57,73.82 115.57,74.14 115.97,74.53 RN2.6
  Bottom 0.254: v115.57,73.82 114.4,75 M1.4
N$12  (via drill 0.3)
  Top 0.61: IC1.15 95.73,59.22 93.82,61.12 v93.82,66.83 | v101.44,64.3 101.44,65.56 Q4.4
  Bottom 0.61: v93.82,66.83 97.31,66.83 99.86,64.3 v101.44,64.3
N$14
  Top 0.254: LED1.C R44.2
N$15
  Top 0.406: 23.66,14.77 15.55,14.77 SW1.3 | 23.66,14.77 IC18.4 | 23.66,14.77 25.56,14.77 | 25.56,14.77 R70.1 | 25.56,14.77 R71.2
N$16  (via drill 0.3)
  Top 0.61: v95.73,64.3 IC1.19
  Bottom 0.61: Q5.4 99.54,63.03 98.27,64.3 v95.73,64.3
N$18  (via drill 0.3)
  Top 0.61: v100.17,59.22 Q6.4 | IC1.14 v92.87,59.22
  Bottom 0.61: v92.87,59.22 v100.17,59.22
N$20
  Top 0.254: IC16.106 69.5,73.63 70.01,74.14 70.64,74.14 71.92,72.87 71.92,70.64 C64.1
N$21
  Top 0.254: LED2.C R45.2
N$22
  Top 0.254: RN15.8 87.24,92.17 88.74,93.66 96.52,93.66 KD.1
N$23
  Top 0.254: KD.3 98.58,93.19 89.06,93.19 87.24,91.36 RN15.7
N$24
  Top 0.254: RN15.6 87.23,90.56 87.63,90.97 98.9,90.97 KD.5
N$25
  Top 0.254: LED3.A R58.1
N$26
  Top 0.254: R55.2 | R55.2 TX.C
N$27  (via drill 0.3)
  Top 0.406: R52.1 112.88,54.77 v110.65,52.55 | v86.04,52.39 82.55,52.39 BUZZ.+
  Bottom 0.406: v86.04,52.39 87.95,52.39 88.27,52.55 97.47,52.55 99.22,52.55 v110.65,52.55
N$28
  Top 0.406: BUZZ.- 69.69,52.55 66.52,52.55 Q32.C
N$29
  Top 0.406: Q32.B R53.2
N$30
  Top 0.254: R56.2 RX.C
N$32
  Top 0.254: R93.1 LED5.A | R93.1
N$33  (via drill 0.3)
  Top 0.61: C4.1 99.86,75.72 IC1.28 v95.73,75.72
  Bottom 0.61: D1.C v95.73,75.72
N$34  (via drill 0.3)
  Top 0.61: v24.29,65.56 IC2.23
  Bottom 0.61: Q9.4 v24.29,65.56
N$35  (via drill 0.3)
  Top 0.61: C5.1 99.86,70.64 IC1.24 v95.73,70.64
  Bottom 0.61: D2.C v95.73,70.64
N$36  (via drill 0.3)
  Top 0.61: IC2.15 24.29,75.72 26.2,73.82 v26.2,68.11 | v18.57,70.64 18.57,69.38 Q10.4
  Bottom 0.61: v26.2,68.11 22.7,68.11 20.16,70.64 v18.57,70.64
N$37  (via drill 0.3)
  Top 0.61: C6.1 99.86,65.56 IC1.20 v95.73,65.56
  Bottom 0.61: D3.C v95.73,65.56
N$38  (via drill 0.3)
  Top 0.61: v24.29,70.64 IC2.19
  Bottom 0.61: v24.29,70.64 21.75,70.64 20.48,71.92 Q11.4
N$40  (via drill 0.3)
  Top 0.61: Q12.4 v19.84,75.72 | v30.01,75.72 IC2.14
  Bottom 0.61: v19.84,75.72 v30.01,75.72
N$41  (via drill 0.3)
  Top 0.61: C12.1 20.16,59.22 IC2.28 v24.29,59.22
  Bottom 0.61: v24.29,59.22 D5.C
N$42  (via drill 0.3)
  Top 0.61: C13.1 20.16,64.3 IC2.24 v24.29,64.3
  Bottom 0.61: v24.29,64.3 D6.C
N$43  (via drill 0.3)
  Top 0.61: C14.1 20.16,69.38 IC2.20 v24.29,69.38
  Bottom 0.61: v24.29,69.38 D7.C
N$44  (via drill 0.3)
  Top 0.61: IC2.16 23.97,74.45 25.24,73.19 25.24,63.98 v24.29,63.03 | v18.57,64.3 18.57,63.03 Q8.4
  Bottom 0.61: v24.29,63.03 23.02,64.3 v18.57,64.3
N$48
  Top 0.406: R7.1 FLT2.C
N$49  (via drill 0.3)
  Top 0.61: v24.29,60.48 IC2.27
  Bottom 0.61: v24.29,60.48 21.75,60.48 20.48,59.22 Q7.4
N$51
  Top 0.254: R1.1 83.56,69.16 FLT1.C
N$53  (via drill 0.3)
  Top 0.61: v24.29,34.45 IC3.23
  Bottom 0.61: Q15.4 v24.29,34.45
N$54  (via drill 0.3)
  Top 0.61: IC3.15 24.29,44.61 26.2,42.7 v26.2,36.99 | v18.57,39.53 18.57,38.26 Q16.4
  Bottom 0.61: v26.2,36.99 22.7,36.99 20.16,39.53 v18.57,39.53
N$55  (via drill 0.3)
  Top 0.61: v24.29,39.53 IC3.19
  Bottom 0.61: v24.29,39.53 21.75,39.53 20.48,40.8 Q17.4
N$56  (via drill 0.3)
  Top 0.61: Q18.4 v19.84,44.61 | v27.47,44.61 IC3.14
  Bottom 0.61: v19.84,44.61 v27.47,44.61
N$57  (via drill 0.3)
  Top 0.61: C20.1 20.16,28.1 IC3.28 v24.29,28.1
  Bottom 0.61: v24.29,28.1 D9.C
N$58  (via drill 0.3)
  Top 0.61: C21.1 20.16,33.18 IC3.24 v24.29,33.18
  Bottom 0.61: v24.29,33.18 D10.C
N$59  (via drill 0.3)
  Top 0.61: C22.1 20.16,38.26 IC3.20 v24.29,38.26
  Bottom 0.61: v24.29,38.26 D11.C
N$60  (via drill 0.3)
  Top 0.61: IC3.16 23.97,43.34 25.24,42.07 25.24,32.86 v24.29,31.91 | v18.57,33.18 18.57,31.91 Q14.4
  Bottom 0.61: v24.29,31.91 23.02,33.18 v18.57,33.18
N$63
  Top 0.406: R13.1 FLT3.C
N$64  (via drill 0.3)
  Top 0.61: v24.29,29.37 IC3.27
  Bottom 0.61: v24.29,29.37 21.75,29.37 20.48,28.1 Q13.4
N$66  (via drill 0.3)
  Top 0.61: v95.73,39.53 IC4.23
  Bottom 0.61: v95.73,39.53 Q21.4
N$67  (via drill 0.3)
  Top 0.61: IC4.15 95.73,29.37 93.82,31.27 v93.82,36.99 | v101.44,34.45 101.44,35.72 Q22.4
  Bottom 0.61: v93.82,36.99 97.63,36.99 100.17,34.45 v101.44,34.45
N$68  (via drill 0.3)
  Top 0.61: v95.73,34.45 IC4.19
  Bottom 0.61: v95.73,34.45 98.27,34.45 99.54,33.18 Q23.4
N$69  (via drill 0.3)
  Top 0.61: v100.17,29.37 Q24.4 | IC4.14 v92.87,29.37
  Bottom 0.61: v92.87,29.37 v100.17,29.37
N$70  (via drill 0.3)
  Top 0.61: C28.1 99.86,45.88 IC4.28 v95.73,45.88
  Bottom 0.61: D13.C v95.73,45.88
N$71  (via drill 0.3)
  Top 0.61: C29.1 99.86,40.8 IC4.24 v95.73,40.8
  Bottom 0.61: D14.C v95.73,40.8
N$72  (via drill 0.3)
  Top 0.61: 99.86,35.09 C30.1 99.86,35.72 IC4.20 v95.73,35.72
  Bottom 0.61: D15.C v95.73,35.72
N$73  (via drill 0.3)
  Top 0.61: IC4.16 96.05,30.64 94.78,31.91 94.78,41.12 v95.73,42.07 | v101.44,40.8 101.44,42.07 Q20.4
  Bottom 0.61: v95.73,42.07 97,40.8 v101.44,40.8
N$75  (via drill 0.3)
  Top 0.254: v112.24,96.05 111.13,96.05 110.91,95.83 IC15.15
  Bottom 0.254: USB1.3 109.06,103.98 109.06,103.03 112.24,99.86 v112.24,96.05
N$78  (via drill 0.3)
  Top 0.254: IC23.3 67.77,11.76 v68.11,11.43 68.74,10.8 69.56,10.8 RN20.8 | CN10.8 78.9,9.89 v78.9,9.05
  Bottom 0.254: v78.9,9.05 78.27,8.41 77.63,8.41 76.2,9.84 69.69,9.84 v68.11,11.43
N$79  (via drill 0.3)
  Top 0.254: IC19.6 48.78,28.42 v49.37,28.42
  Bottom 0.254: v49.37,28.42 50.01,27.78 SJ1.2
N$80
  Top 0.406: FLT4.C 96.78,25.78 R19.1
N$81  (via drill 0.3)
  Top 0.254: IC15.23 108.45,90.62 v107.47,91.6 | v98.43,106.84 R55.1
  Bottom 0.254: v107.47,91.6 107.47,100.17 105.25,102.39 103.03,102.39 98.58,106.84 v98.43,106.84
N$83  (via drill 0.3)
  Top 0.61: v95.73,44.61 IC4.27
  Bottom 0.61: v95.73,44.61 98.27,44.61 99.54,45.88 Q19.4
N$84  (via drill 0.3)
  Top 0.254: 73.82,18.33 IC24.12 73.81,19.07 73.5,19.37 | RN23.3 69.62,19.76 v70.01,19.37 73.5,19.37 | CN13.3 74.06,19.93 73.5,19.37
N$85  (via drill 0.3)
  Top 0.254: IC24.14 IC24.13 73.19,18.26 v73.19,17.3 | RN22.1 82.76,16.19 v82.08,16.19
  Bottom 0.254: v73.19,17.3 78.11,17.3 79.22,16.19 v82.08,16.19
N$87  (via drill 0.3)
  Top 0.254: IC24.3 73.81,13.19 73.5,13.5 72.39,13.5 v71.76,12.86 71.76,11.39 RN20.6 | CN10.6 77.23,10.4 77,10.64 75.88,10.64 v75.57,10.95
  Bottom 0.254: v75.57,10.95 75.41,10.8 73.03,10.8 71.76,12.07 v71.76,12.86
N$88  (via drill 0.3)
  Top 0.254: IC24.1 IC24.2 73.16,11.78 v73.5,11.43 | RN21.2 82.91,9.21 v82.08,9.21
  Bottom 0.254: v73.5,11.43 73.5,12.86 74.77,14.13 77.15,14.13 v82.08,9.21
N$89  (via drill 0.3)
  Top 0.61: v24.29,94.78 IC5.23
  Bottom 0.61: Q27.4 v24.29,94.78
N$90
  Top 0.254: IC24.5 75.09,12.47 75.09,11.75 74.45,11.11 | RN20.5 73,10.8 74.14,10.8 74.45,11.11 | CN10.5 75.61,9.96 74.45,11.11
N$91  (via drill 0.3)
  Top 0.254: IC24.6 IC24.7 76.36,12.54 v76.36,13.5 | RN21.3 82.91,8.26 v82.08,8.26
  Bottom 0.254: v82.08,8.26 76.84,13.5 v76.36,13.5
N$92  (via drill 0.3)
  Top 0.61: Q28.4 18.57,98.58 v18.57,99.54 | v26.2,97.31 26.2,103.03 24.29,104.94 IC5.15
  Bottom 0.61: v18.57,99.54 20.48,99.54 22.7,97.31 v26.2,97.31
N$93  (via drill 0.3)
  Top 0.61: v24.29,99.86 IC5.19
  Bottom 0.61: v24.29,99.86 21.75,99.86 20.48,101.12 Q29.4
N$95  (via drill 0.3)
  Top 0.61: Q30.4 v19.84,104.94 | v27.15,104.94 IC5.14
  Bottom 0.61: v19.84,104.94 v27.15,104.94
N$96  (via drill 0.3)
  Top 0.61: C36.1 20.16,88.42 IC5.28 v24.29,88.42
  Bottom 0.61: v24.29,88.42 D17.C
N$97  (via drill 0.3)
  Top 0.61: C37.1 20.16,93.5 21.75,93.5 IC5.24 v24.29,93.5
  Bottom 0.61: v24.29,93.5 D18.C
N$99  (via drill 0.3)
  Top 0.61: C38.1 20.16,98.58 IC5.20 v24.29,98.58
  Bottom 0.61: v24.29,98.58 D19.C
N$101  (via drill 0.3)
  Top 0.254: IC15.22 109.07,91.28 v108.11,92.23 | v98.43,111.28 R56.1
  Bottom 0.254: v108.11,92.23 108.11,100.49 105.57,103.03 104.3,103.03 98.43,108.9 v98.43,111.28
N$105
  Top 0.254: IC10.11 IC10.10
N$106
  Top 0.254: IC11.11 IC11.10
N$107
  Top 0.254: IC11.3 39.52,84.6 39.85,84.93 40.48,84.93 40.81,84.6 IC11.5
N$108
  Top 0.254: IC10.5 80.82,68.09 80.49,68.42 79.85,68.42 79.52,68.09 IC10.3
N$109
  Top 0.254: IC12.6 43.05,93.47 43.34,93.19 43.98,93.19 44.29,93.5 44.29,95.09 42.39,97 42.39,99.9 IC12.10
N$114  (via drill 0.3)
  Top 0.254: IC9.4 51.28,46.2 C49.1 R49.1 v35.09,50.01
  Bottom 0.254: v35.09,50.01 33.82,51.28 9.68,51.28 5.88,55.09 5.88,57.94 BD.2
N$115  (via drill 0.3)
  Top 0.254: IC21.6 48.78,12.54 v49.37,12.54
  Bottom 0.254: v49.37,12.54 50.01,11.91 SJ2.2
N$116  (via drill 0.3)
  Top 0.254: IC23.1 IC23.2 67.15,12.54 v67.15,13.5 | RN22.4 82.76,13.34 v82.08,13.34
  Bottom 0.254: v67.15,13.5 69.06,15.4 77.63,15.4 79.69,13.34 v82.08,13.34
N$118  (via drill 0.3)
  Top 0.254: IC23.5 69.07,13.19 69.38,13.5 70.49,13.5 71.12,12.86 v71.12,12.23 70.96,12.07 70.96,11.39 RN20.7 | CN10.7 77.95,9.88 v77.95,9.05
  Bottom 0.254: v77.95,9.05 76.68,10.32 72.55,10.32 71.12,11.75 v71.12,12.23
N$119  (via drill 0.3)
  Top 0.254: 69.69,12.54 IC23.6 | 69.69,12.54 70.31,12.54 IC23.7 | 69.69,12.54 69.69,11.91 v69.22,11.43 | RN21.1 82.6,10.16 v82.08,10.16
  Bottom 0.254: v69.22,11.43 72.55,14.77 77.47,14.77 v82.08,10.16
N$120
  Top 0.254: LED4.A R59.1
N$122  (via drill 0.3)
  Top 0.254: IC23.10 69.07,19.2 v68.9,19.37 68.82,19.45 RN23.2 68.82,20.56 69.22,20.96 73.03,20.96 73.26,20.72 CN13.2
N$123  (via drill 0.3)
  Top 0.254: 69.69,18.26 IC23.9 | v69.69,17.3 69.69,18.26 | 69.69,18.26 69.75,18.32 IC23.8 | RN22.2 82.91,15.24 v82.08,15.24
  Bottom 0.254: v69.69,17.3 70.33,16.67 77.95,16.67 79.38,15.24 v82.08,15.24
N$124  (via drill 0.3)
  Top 0.254: RN4.6 5.24,81.4 v5.24,82.08
  Bottom 0.254: M2.2 6,81 5.24,81.76 v5.24,82.08
N$125  (via drill 0.3)
  Top 0.254: RN23.1 68.02,19.6 v67.79,19.37 67.77,19.35 IC23.12 | CN13.1 72.34,20.16 v71.6,20.16
  Bottom 0.254: v71.6,20.16 68.58,20.16 v67.79,19.37
N$126  (via drill 0.3)
  Top 0.254: IC23.14 IC23.13 67.15,18.26 v67.15,17.3 | RN22.3 82.91,14.29 v82.08,14.29
  Bottom 0.254: v67.15,17.3 68.42,16.04 77.79,16.04 79.53,14.29 v82.08,14.29
N$127  (via drill 0.3)
  Top 0.254: RN4.8 3.34,81.23 v3.34,82.08
  Bottom 0.254: v3.34,82.08 3.34,81.76 5.56,79.53 6.1,79 M2.4
N$147  (via drill 0.3)
  Top 0.61: Q26.4 18.57,92.23 v18.57,93.19 | v24.29,92.23 25.24,93.19 25.24,102.39 23.97,103.67 IC5.16
  Bottom 0.61: v18.57,93.19 23.34,93.19 v24.29,92.23
N$148  (via drill 0.3)
  Top 0.254: RN4.7 4.29,81.25 v4.29,82.08
  Bottom 0.254: v4.29,82.08 4.29,81.44 5.73,80 M2.3
N$150
  Top 0.254: R74.1 50.33,26.51 50.01,26.51 48.78,25.29 IC19.5 | R74.1 | R74.1 51.12,26.35 52.55,26.35 C86.1
N$151
  Top 0.254: IC19.9 47.28,29.98 48.58,31.27 R76.2
N$153
  Top 0.254: LED5.C 84.83,3.55 86.2,4.92 90.7,4.92 IC25.1
N$155
  Top 0.254: R54.2 C56.2
N$157  (via drill 0.3)
  Top 0.61: IC18.5 v23.66,20.16
  Bottom 0.406: 30.23,20.16 Q34.1
  Bottom 0.61: v23.66,20.16 30.23,20.16
N$158
  Top 0.406: FLT5.C 26.93,84.3 R25.1
N$162  (via drill 0.3)
  Top 0.61: v24.29,89.69 IC5.27
  Bottom 0.61: v24.29,89.69 21.75,89.69 20.48,88.42 Q25.4
N$165
  Top 0.254: R60.2 58.26,100.49 59.53,99.22 59.53,95.73 59,95.2 IC16.24
N$167
  Top 0.254: RN24.3 CN14.2
N$168
  Top 0.254: IC16.23 59.5,95.06 60.17,95.73 60.17,99.54 59.53,100.17 59.53,102.08 59.53,104.46 | 59.53,104.46 59.53,105.25 Q33.1 | C79.1 61.91,104.46 59.53,104.46
N$169
  Top 0.254: 56.36,104.46 R60.1 | 56.36,104.46 56.36,105.25 Q33.2 | C80.1 53.98,104.46 56.36,104.46
N$170
  Top 0.254: RN24.2 CN14.3
N$172
  Top 0.254: RN24.1 CN14.4
N$173
  Top 0.254: JTAG.11 86.64,99.86 RN19.7
N$174
  Top 0.254: R77.2 43.02,30.64 43.18,30.64 43.82,30.01 46.76,30.01 46.76,29.05 IC19.10
N$175
  Top 0.254: R76.1 46.2,30.95 C88.1
N$176  (via drill 0.3)
  Top 0.254: IC13.14 57.66,64.33 v57.31,63.98 | v57.31,61.75 57.31,60.81 C55.1 C56.1
  Bottom 0.254: v57.31,61.75 v57.31,63.98
N$179  (via drill 0.3)
  Top 0.254: v111.6,95.41 111.37,95.17 IC15.16
  Bottom 0.254: USB1.2 108.11,104.16 108.11,102.71 111.6,99.22 v111.6,95.41
N$180
  Top 0.254: IC16.71 49.69,75.09 49.37,75.41 45.25,75.41 C63.1
N$181
  Top 0.254: R51.2 59.85,52.23 60.8,52.23 61.12,52.55 Q31.B
N$182  (via drill 0.3)
  Top 0.254: v35.09,51.28 53.5,51.28 56.04,53.82 R50.2
  Bottom 0.254: v35.09,51.28 34.45,51.91 10,51.91 6.51,55.41 6.51,62.39 BD.4
N$184
  Top 0.254: R50.1 59.85,54.45 61.75,54.45 62.07,54.77 Q31.C
N$185
  Top 0.254: IC9.1 54.14,44.29 54.45,44.61 54.45,45.24 55.09,45.88 55.41,45.88 | 55.41,45.88 R48.1 | R49.2 C49.2 54.61,46.67 55.25,46.67 55.41,46.51 55.41,45.88
N$187
  Top 0.254: R80.1 45.24,27.15 46.2,28.1 48.28,28.1 IC19.7
N$197
  Top 0.254: C84.1 46.52,23.02 47.28,23.79 IC19.2
N$198
  Top 0.254: 47.78,19.21 IC19.3 | 47.78,19.21 46.83,19.21 C84.2 44.93,19.53 43.02,17.62 42.07,17.62 L2.P$2 | D23.C 49.05,18.57 48.42,19.21 47.78,19.21
  pour Top (no thermals): 40.16,18.26 43.02,18.26 44.93,20.16 50.64,20.16 50.64,17.3 45.24,17.3 44.61,16.67 40.16,16.67
N$200
  Top 0.254: IC19.8 47.78,29.69 48.26,30.16 49.69,30.16 | 49.69,30.16 R78.2 | R75.1 49.69,31.12 49.69,30.16
N$201
  Top 0.254: IC21.9 47.28,14.11 48.58,15.4 R85.2
N$202
  Top 0.254: R86.2 43.02,14.77 43.18,14.61 43.5,14.61 43.98,14.13 46.76,14.13 46.76,13.18 IC21.10
N$203
  Top 0.254: R85.1 46.2,15.08 45.24,15.08 C93.1
N$204
  Top 0.254: R90.1 45.24,11.59 45.88,11.59 46.52,12.23 48.28,12.23 IC21.7
N$205
  Top 0.254: C89.1 46.52,7.14 47.28,7.91 IC21.2
N$206
  Top 0.254: 47.78,3.34 IC21.3 | 47.78,3.34 46.83,3.34 C89.2 44.93,3.65 43.34,2.06 42.39,2.06 L3.P$2 | D24.C 49.37,3.02 49.05,3.34 47.78,3.34
  pour Top (no thermals): 40.16,2.38 43.02,2.38 44.93,4.29 50.64,4.29 50.64,1.43 45.24,1.43 44.61,0.79 40.16,0.79
N$207
  Top 0.254: IC21.8 47.78,13.81 48.26,14.29 49.69,14.29 | R84.1 50.17,15.4 49.69,14.93 49.69,14.29 | 49.69,14.29 R88.2
N$216  (via drill 0.3)
  Top 0.254: RN6.8 7.99,18.57 v7.14,18.57
  Bottom 0.254: v7.14,18.57 6,19.72 6,21.88 6.32,22.2 M3.2
N$217  (via drill 0.3)
  Top 0.254: RN6.6 7.82,20.48 v7.14,20.48
  Bottom 0.254: v7.14,20.48 8.32,21.66 M3.4
N$222  (via drill 0.3)
  Top 0.254: RN6.7 7.98,19.53 v7.14,19.53
  Bottom 0.254: v7.14,19.53 6.51,20.16 6.51,20.96 7.32,21.77 M3.3
N$237  (via drill 0.3)
  Top 0.254: RN8.6 105.3,20.8 v104.62,20.8
  Bottom 0.254: v104.62,20.8 105.38,21.56 M4.2
N$238  (via drill 0.3)
  Top 0.254: RN8.8 105.46,18.89 v104.62,18.89
  Bottom 0.254: v104.62,18.89 104.94,18.89 107.16,21.11 107.16,22.23 107.38,22.45 M4.4
N$243  (via drill 0.3)
  Top 0.254: RN8.7 105.45,19.84 v104.62,19.84
  Bottom 0.254: v104.62,19.84 105.09,19.84 106.38,21.13 M4.3
N$258
  Top 0.254: M5.2 4.92,103.35 9.68,108.11 10.83,108.11 RN10.6
N$259
  Top 0.254: M5.4 6.51,101.44 6.51,103.03 10,106.52 10.84,106.52 RN10.8
N$264
  Top 0.254: M5.3 10,107.47 10.83,107.47 RN10.7
PADC-VOP
  Top 0.254: 79.53,14.45 C94.1 77.95,14.45 | 74.45,14.45 77.95,14.45 | 77.95,14.45 79.53,14.45 | IC23.4 68.42,14.45 74.45,14.45 | 74.45,14.45 IC24.4 | 79.53,14.45 79.85,14.45 R91.2
PWR-AREF
  Top 0.254: C99.1 D25.1 87.47,20.96 87.31,20.96 85.57,22.7 85.57,23.34 84.61,24.29 C98.+ 84.84,24.92 R94.1 | C99.1 92.87,20.8 | C99.1 93.91,19.44 IC25.20
PWR-AVCC
  Top 0.254: L4.2 91.6,22.55 | L4.2 91.77,23.02 C97.1 R94.2 | L4.2 92.7,22.87 95.5,20.07 IC25.18
PWR-CS  (via drill 0.3)
  Top 0.254: IC25.14 96.93,10.89 96.68,10.64 v94.14,10.64 | IC16.103 68,70.75 v68.11,70.64
  Bottom 0.254: v94.14,10.64 94.14,19.21 82.08,31.27 82.08,46.52 82.71,47.15 82.71,50.17 83.82,51.28 83.82,57.31 82.71,58.42 82.71,60.8 73.19,70.33 68.42,70.33 v68.11,70.64
PWR-RST  (via drill 0.3)
  Top 0.254: R92.1 C95.1 v100.17,14.45 | v94.78,10 91.6,10 90.88,9.29 IC25.29 | IC16.104 68.5,71.52 v69.06,70.96
  Bottom 0.254: v69.06,70.96 73.5,70.96 83.34,61.12 83.34,58.58 84.3,57.63 84.3,50.96 83.34,50.01 83.34,46.99 82.71,46.36 82.71,31.59 94.78,19.53 v94.78,10 95.73,10 v100.17,14.45
PWR-XTAL
  Top 0.254: IC25.7 95.57,5.33 95.57,4.61 95.89,4.29 96.68,4.29 97.95,5.56 102.71,5.56 104.3,7.14 QG2.3
SPI1-MISO
  Top 0.254: IC16.42 48.95,89.59 48.42,89.06 46.83,89.06 45.4,90.49 45.4,93.82 46.36,94.78 46.36,100.65 42.07,104.94 36.2,104.94 33.97,107.16 31.59,107.16 WF1.7
SPI1-MOSI
  Top 0.254: IC16.43 49.09,89.09 48.42,88.42 46.83,88.42 44.77,90.49 44.77,100.97 41.75,103.98 35.88,103.98 33.66,106.2 30.48,106.2 29.21,107.47 29.21,110.81 30.16,111.76 32.07,111.76 WF1.6
SPI1-SCK
  Top 0.254: IC16.41 48.82,90.09 48.42,89.69 46.83,89.69 45.88,90.65 45.88,93.66 46.83,94.62 46.83,100.81 42.23,105.41 36.35,105.41 33.66,108.11 WF1.5
SPI2-MISO  (via drill 0.3)
  Top 0.203: IC14.7 60,56.51 v59.85,56.36
  Top 0.254: IC13.4 60.97,64.44 v60.8,64.61 | v54.77,69.38 54,70.14 IC16.75
  Bottom 0.203: v59.85,56.36 60.8,57.31 v60.8,64.61
  Bottom 0.254: v60.8,64.61 58.58,66.83 57.31,66.83 v54.77,69.38
SPI2-MOSI  (via drill 0.3)
  Top 0.203: IC14.6 59.5,57.28 v59.22,56.99
  Top 0.254: IC13.3 60.33,63.82 v60.17,63.98 | IC16.76 54.5,70.59 55.41,69.69 v55.41,67.79
  Bottom 0.203: v59.22,56.99 60.17,57.94 v60.17,63.98
  Bottom 0.254: v60.17,63.98 57.94,66.2 56.99,66.2 v55.41,67.79
SPI2-SCK  (via drill 0.3)
  Top 0.203: IC14.4 58.03,58.5 v57.94,58.58
  Top 0.254: IC13.2 59.67,63.2 v59.53,63.34 | v54.14,68.11 53.5,68.74 53.5,72.55 53.51,72.56 IC16.74
  Bottom 0.203: v57.94,58.58 58.58,58.58 59.53,59.53 v59.53,63.34
  Bottom 0.254: v59.53,63.34 57.31,65.56 56.67,65.56 v54.14,68.11
SPI3-MISO  (via drill 0.3)
  Top 0.254: IC25.16 96.62,12.48 96.05,11.91 v92.87,11.91 | IC16.112 73.77,76.09 74.45,75.41 v74.45,74.14 v74.45,68.11 | IC8.16 71.23,42.23 v74.45,42.23 | RN15.2 84.38,91.36 v83.66,90.65 | RN24.7 99.42,3.02 v98.58,3.02
  Bottom 0.254: v74.45,74.14 75.72,74.14 83.66,82.08 v83.66,90.65 | v74.45,68.11 74.14,68.11 71.28,65.25 71.28,60.17 74.3,57.15 74.3,45.4 74.45,45.24 v74.45,42.23 74.45,36.99 92.87,18.57 v92.87,11.91 92.87,8.73 v98.58,3.02
SPI3-MOSI  (via drill 0.3)
  Top 0.254: IC25.15 96.78,11.68 96.36,11.27 v93.5,11.27 | IC16.113 73.9,76.59 75.09,75.41 v75.09,73.5 v75.09,67.47 | IC8.15 71.22,41.44 v75.09,41.44 | RN15.3 84.85,90.56 v84.3,90.01 | RN24.6 99.26,3.97 v98.58,3.97
  Bottom 0.254: v75.09,73.5 75.72,73.5 84.3,82.08 v84.3,90.01 | v75.09,67.47 74.45,67.47 71.92,64.93 71.92,60.48 74.77,57.63 74.77,45.72 75.09,45.4 v75.09,41.44 75.09,37.31 93.5,18.89 v93.5,11.27 93.5,9.05 v98.58,3.97
SPI3-SCK  (via drill 0.3)
  Top 0.254: IC25.17 96.31,13.12 95.73,12.54 v92.23,12.54 | IC16.111 73.63,75.59 73.82,75.41 v73.82,74.77 v73.82,68.74 | IC8.17 69.69,43.88 69.69,43.34 70.01,43.02 73.66,43.02 v73.82,42.86 | RN15.1 83.91,92.17 v83.03,91.28 | RN24.8 99.43,2.06 v98.58,2.06
  Bottom 0.254: v73.82,74.77 75.72,74.77 83.03,82.08 v83.03,91.28 | 92.23,9.68 | 92.23,9.68 v92.23,12.54 92.23,18.26 73.82,36.67 v73.82,42.86 73.82,50.8 70.49,54.14 70.49,59.69 70.64,59.85 70.64,65.56 v73.82,68.74 | v98.58,2.06 92.23,8.41 92.23,9.68 | 92.23,9.68 | 92.23,9.68
SRST  (via drill 0.3)
  Top 0.254: C77.1 58.26,96.68 58.26,95.41 58.5,95.17 IC16.25 58.5,92.63 v58.9,92.23 | v77,95.09 77.15,95.25 85.13,95.25 RN18.2 85.65,95.17 85.89,95.41 85.89,98.9 86.12,99.14 RN19.6 86.64,99.06 87.95,99.06 88.42,98.58 97.95,98.58 107.39,108.03 RESET.3 RESET.4 | RESET.4
  Bottom 0.254: v58.9,92.23 62.39,92.23 66.83,87.79 70.01,87.79 71.6,89.38 71.6,89.69 v77,95.09 77,103.67 71.28,109.38 EXT.11
TCK  (via drill 0.3)
  Top 0.254: IC16.109 70.82,74.59 70.01,75.41 70.01,77.63 66.83,80.81 v66.83,86.52 | v79.85,103.03 85.14,103.03 RN17.4
  Bottom 0.254: v66.83,86.52 70.64,86.52 72.87,88.74 72.87,89.06 76.04,92.23 77.31,92.23 79.85,94.78 v79.85,103.03 79.85,107.16 EXT.15
TDI  (via drill 0.3)
  Top 0.254: IC16.110 71.28,75.09 70.64,75.72 70.64,77.95 67.47,81.12 v67.47,87.16 | v79.22,104.62 85.13,104.62 RN17.2
  Bottom 0.254: v67.47,87.16 70.33,87.16 72.23,89.06 72.23,89.38 79.22,96.36 v79.22,104.62
TDO-EXT
  Top 0.254: RN18.1 84.05,95.97 78.58,101.44 78.58,105.89 EXT.13
TDO-M4  (via drill 0.3)
  Top 0.254: IC16.133 70.57,86.59 70.01,87.16 v70.01,89.06
  Bottom 0.254: v70.01,89.06 70.33,89.06 70.96,89.69 70.96,90.01 76.36,95.41 76.36,103.35 69.69,110.02 69.38,110.02 EXT.9
TMS  (via drill 0.3)
  Top 0.254: v66.2,85.89 66.2,80.49 69.38,77.31 69.38,74.14 69,73.77 IC16.105 | v80.49,103.82 85.13,103.82 RN17.3
  Bottom 0.254: v66.2,85.89 70.96,85.89 73.5,88.42 73.5,88.74 76.36,91.6 77.63,91.6 80.49,94.46 v80.49,103.82 80.49,109.06 EXT.17
TRST  (via drill 0.3)
  Top 0.254: v78.9,87.79 74.77,87.79 74.08,87.09 IC16.134 | v81.12,105.41 85.12,105.41 RN17.1
  Bottom 0.254: EXT.19 81.12,110.33 v81.12,105.41 81.12,94.14 78.9,91.92 v78.9,87.79
USART1-RX  (via drill 0.3)
  Top 0.254: IC16.102 67.5,75.76 v68.74,77 | v75.09,78.58 76.52,77.15 79.69,77.15 82.71,80.17 99.38,80.17 105.57,86.36 112.24,86.36 113.25,87.38 IC15.1
  Bottom 0.254: v68.74,77 70.33,78.58 v75.09,78.58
